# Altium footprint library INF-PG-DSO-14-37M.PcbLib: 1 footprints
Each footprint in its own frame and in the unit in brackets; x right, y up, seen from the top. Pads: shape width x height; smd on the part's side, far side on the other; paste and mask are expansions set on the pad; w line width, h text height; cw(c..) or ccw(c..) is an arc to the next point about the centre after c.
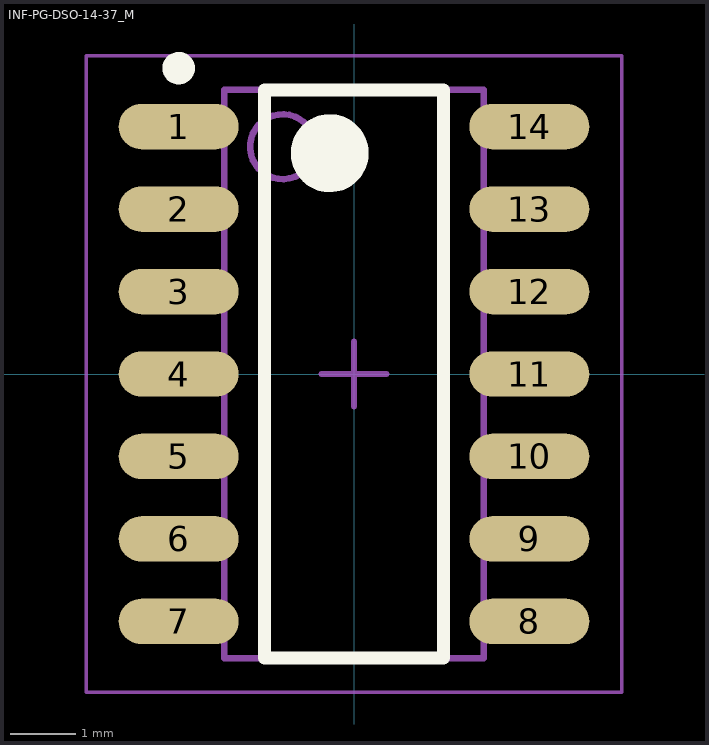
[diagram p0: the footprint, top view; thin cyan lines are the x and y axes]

## INF-PG-DSO-14-37_M [mm] "SOP, 14-Leads, Body 8.65x3.9mm, Pitch 1.27mm, IPC Low Density"
height 1.75
pads (14):
  oval 1.85x0.7 smd: 1(-2.7,3.81) 2(-2.7,2.54) 3(-2.7,1.27) 4(-2.7,0) 5(-2.7,-1.27) 6(-2.7,-2.54) 7(-2.7,-3.81) 8(2.7,-3.81) 9(2.7,-2.54) 10(2.7,-1.27) 11(2.7,0) 12(2.7,1.27) 13(2.7,2.54) 14(2.7,3.81)
Top Overlay:
  circle w0.25: c-2.7,4.71 r0.125
  circle w0.6: c-0.375,3.4 r0.3
  lines w0.2: -1.375,-4.375 -1.375,4.375 1.375,4.375 1.375,-4.375 -1.375,-4.375
Mechanical 13:
  circle w0.1: c-1.1,3.5 r0.5
  lines w0.1: -2,-4.375 -2,4.375 2,4.375 2,-4.375 -2,-4.375
Mechanical 15:
  lines w0.05: -4.125,-4.9 -4.125,4.9 4.125,4.9 4.125,-4.9 -4.125,-4.9
  lines w0.1: -0.5,0 0.5,0 ; 0,-0.5 0,0.5
3D body: height 1.75, standoff 0.11, extent -2,-4.375 2,4.375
